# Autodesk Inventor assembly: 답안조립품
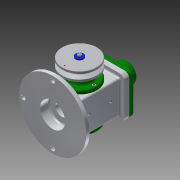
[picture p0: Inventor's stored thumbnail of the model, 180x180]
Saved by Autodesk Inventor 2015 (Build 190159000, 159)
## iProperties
Created: 2019-08
Part Number: 답안조립품
Document SubType Name: Assembly
Designer: a-20
Author: a-20
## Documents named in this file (18)
- C:\Users\a-20\Desktop\490804V1004\답안조립품.iam
- C:\Users\a-20\Desktop\490804V1004\본체.ipt
- C:\Users\a-20\Desktop\490804V1004\베어링 17 x 40 x 12.ipt
- C:\Users\a-20\Desktop\490804V1004\뒤커버.ipt
- C:\Users\a-20\Desktop\490804V1004\앞커버.ipt
- C:\Users\a-20\Desktop\490804V1004\편심축.ipt
- C:\Users\a-20\Desktop\490804V1004\클레비스 핀 6 x 22.ipt
- 클레비스 핀 6 x 22.ipt
- C:\Users\a-20\Desktop\490804V1004\슬라이더.ipt
- C:\Users\a-20\Desktop\490804V1004\덮개.ipt
- C:\Users\a-20\Desktop\490804V1004\링크.ipt
- C:\Users\a-20\Desktop\490804V1004\V-벨트풀리.ipt
- C:\Users\a-20\Desktop\490804V1004\키 4 x 4 x 12.ipt
- C:\Users\a-20\Desktop\490804V1004\와셔 4x16.ipt
- C:\Users\a-20\Desktop\490804V1004\볼트 M4 x 10.ipt
- C:\Users\a-20\Desktop\490804V1004\E-링.ipt
- C:\Users\a-20\Desktop\490804V1004\오일 실 17 30 8.ipt
- C:\Users\a-20\Desktop\490804V1004\볼트 M4 x 8.ipt
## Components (2 placed, 2 different names)
1. V-벨트풀리:1
2. E-링:1
